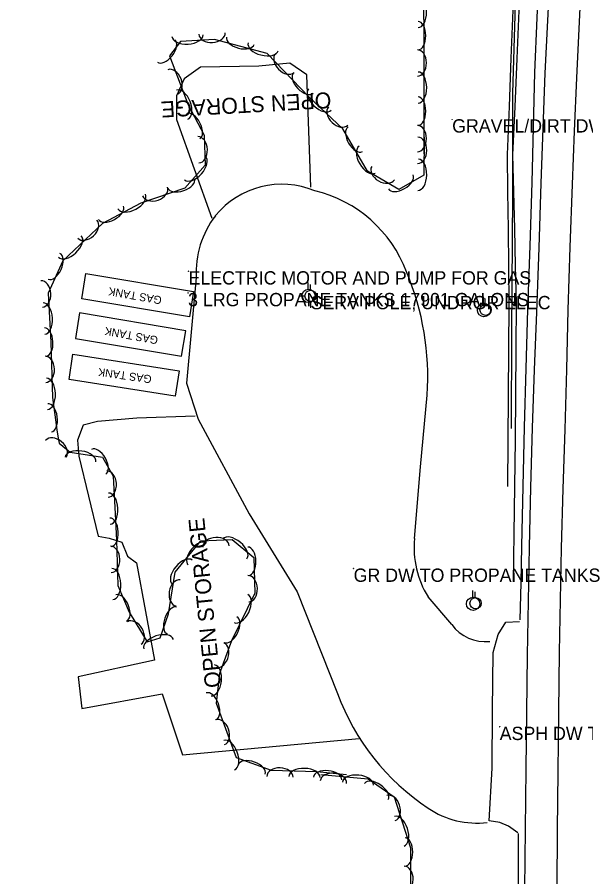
# Model space of a CAD drawing. Extents: x 954793 to 988390, y 1867850 to 1924428.
# Drawn here: x 960777.6 to 960991.5, y 1905142.2 to 1905465.6 of the extents above; entities that cross this region are included whole.
import ezdxf

# ---------------------------------------------------------------- set-up
doc = ezdxf.new("R2010")
doc.units = 0
for name, color, linetype in [('S_DITCHLINE', 7, 'Continuous'), ('S_DRIVEWAY', 7, 'Continuous'), ('S_EDGE_PAVEMENT', 7, 'Continuous'), ('S_MISC_BOUNDARY', 7, 'Continuous'), ('S_MISC_BOUNDARY_ANNOT', 7, 'Continuous'), ('S_MSC_PT_SYM', 7, 'Continuous'), ('S_PARKING', 7, 'Continuous'), ('S_PAVEMENT_CROWN', 7, 'Continuous'), ('S_SHOULDER', 7, 'Continuous'), ('S_STREAM', 7, 'Continuous'), ('S_SURVEY_TEXT_ANNOT', 7, 'Continuous'), ('S_TANK', 7, 'Continuous'), ('S_TANK_ANNOT', 7, 'Continuous'), ('S_TREE', 7, 'Continuous'), ('S_UTILITY_POLE', 7, 'Continuous'), ('S_UTILITY_POLE_ANNOT', 7, 'Continuous')]:
    doc.layers.add(name, color=color, linetype=linetype)

msp = doc.modelspace()

# ---------------------------------------------------------------- linework, layer by layer
at = {"layer": 'S_DITCHLINE'}
for points in [[(960962.25, 1905289.04), (960962.35, 1905306.2), (960962.45, 1905323.37), (960962.55, 1905340.53), (960962.65, 1905357.7), (960962.51, 1905371.75), (960962.38, 1905385.8), (960962.24, 1905399.85), (960962.1, 1905413.9), (960962.8, 1905432.03), (960963.49, 1905450.16), (960964.19, 1905468.29), (960964.88, 1905486.43), (960966.76, 1905510.29), (960968.63, 1905534.15)], [(960964.36, 1905253.1), (960964.62, 1905271.14), (960964.88, 1905289.19), (960965.02, 1905306.4), (960965.15, 1905323.62), (960965.29, 1905340.84), (960965.42, 1905358.06), (960965.09, 1905371.99), (960964.76, 1905385.92), (960964.43, 1905399.86), (960964.1, 1905413.79), (960964.91, 1905431.9), (960965.71, 1905450.02), (960966.51, 1905468.14), (960967.32, 1905486.25), (960968.34, 1905510.11), (960969.37, 1905533.98)]]:
    msp.add_lwpolyline(points, dxfattribs=at)
at = {"layer": 'S_DRIVEWAY'}
msp.add_lwpolyline([(960965.96, 1905158.68), (960962.44, 1905161.19), (960959.2, 1905162.58), (960955.21, 1905163.24), (960956.28, 1905183.02), (960956.45, 1905204.76), (960956.63, 1905226.51), (960958.57, 1905233.38), (960961.39, 1905237.96), (960966.56, 1905238.26)], dxfattribs=at)
at = {"layer": 'S_EDGE_PAVEMENT'}
msp.add_lwpolyline([(960968.57, 1905137.51), (960968.84, 1905160.09), (960969.11, 1905182.67), (960969.36, 1905204.08), (960969.61, 1905225.49), (960969.95, 1905245.86), (960970.29, 1905266.23), (960970.88, 1905288.65), (960971.46, 1905311.08), (960972.28, 1905332.87), (960973.1, 1905354.65), (960973.92, 1905378.86), (960974.74, 1905403.08), (960975.48, 1905423.82), (960976.22, 1905444.57), (960977.2, 1905464.29), (960978.18, 1905484.02)], dxfattribs=at)
at = {"layer": 'S_MISC_BOUNDARY'}
for points in [[(960888.11, 1905401.65), (960886.59, 1905443.88), (960880.21, 1905448.32), (960868.47, 1905447.14), (960846.57, 1905446.77), (960840.41, 1905442.41), (960837.55, 1905435.94), (960837.51, 1905427.15), (960850.82, 1905389.99)], [(960844.6, 1905315.42), (960822.58, 1905314.75), (960807.79, 1905313.46), (960802.37, 1905312.1), (960800.25, 1905306.44), (960800.76, 1905300.43), (960807.99, 1905270.34), (960812.19, 1905269.6), (960816.96, 1905268.03), (960819.1, 1905262.78), (960822.5, 1905260.23), (960829.21, 1905223.61), (960800.53, 1905217.36), (960801.96, 1905205.5), (960832.13, 1905211), (960839.76, 1905188.11), (960906.22, 1905194.2)]]:
    msp.add_lwpolyline(points, dxfattribs=at)
at = {"layer": 'S_MSC_PT_SYM'}
for points in [[(960941.25, 1905427.19), (960941.25, 1905427.24), (960941.25, 1905427.19), (960941.2, 1905427.19), (960941.25, 1905427.19), (960941.25, 1905427.14), (960941.25, 1905427.19), (960941.3, 1905427.19)], [(960941.25, 1905427.19), (960941.25, 1905427.24), (960941.25, 1905427.19), (960941.2, 1905427.19), (960941.25, 1905427.19), (960941.25, 1905427.14), (960941.25, 1905427.19), (960941.3, 1905427.19)], [(960842.05, 1905370.01), (960842.05, 1905370.06), (960842.05, 1905370.01), (960842, 1905370.01), (960842.05, 1905370.01), (960842.05, 1905369.96), (960842.05, 1905370.01), (960842.1, 1905370.01)], [(960842.05, 1905370.01), (960842.05, 1905370.06), (960842.05, 1905370.01), (960842, 1905370.01), (960842.05, 1905370.01), (960842.05, 1905369.96), (960842.05, 1905370.01), (960842.1, 1905370.01)], [(960841.88, 1905361.83), (960841.88, 1905361.88), (960841.88, 1905361.83), (960841.83, 1905361.83), (960841.88, 1905361.83), (960841.88, 1905361.78), (960841.88, 1905361.83), (960841.93, 1905361.83)], [(960841.88, 1905361.83), (960841.88, 1905361.88), (960841.88, 1905361.83), (960841.83, 1905361.83), (960841.88, 1905361.83), (960841.88, 1905361.78), (960841.88, 1905361.83), (960841.93, 1905361.83)], [(960904.16, 1905258.14), (960904.16, 1905258.19), (960904.16, 1905258.14), (960904.11, 1905258.14), (960904.16, 1905258.14), (960904.16, 1905258.09), (960904.16, 1905258.14), (960904.21, 1905258.14)], [(960904.16, 1905258.14), (960904.16, 1905258.19), (960904.16, 1905258.14), (960904.11, 1905258.14), (960904.16, 1905258.14), (960904.16, 1905258.09), (960904.16, 1905258.14), (960904.21, 1905258.14)], [(960959.13, 1905198.61), (960959.13, 1905198.66), (960959.13, 1905198.61), (960959.08, 1905198.61), (960959.13, 1905198.61), (960959.13, 1905198.56), (960959.13, 1905198.61), (960959.18, 1905198.61)], [(960959.13, 1905198.61), (960959.13, 1905198.66), (960959.13, 1905198.61), (960959.08, 1905198.61), (960959.13, 1905198.61), (960959.13, 1905198.56), (960959.13, 1905198.61), (960959.18, 1905198.61)]]:
    msp.add_lwpolyline(points, close=True, dxfattribs=at)
for points in [[(960941.25, 1905427.19), (960941.25, 1905427.24), (960941.25, 1905427.19), (960941.2, 1905427.19), (960941.25, 1905427.19), (960941.25, 1905427.14), (960941.25, 1905427.19), (960941.3, 1905427.19)], [(960842.05, 1905370.01), (960842.05, 1905370.06), (960842.05, 1905370.01), (960842, 1905370.01), (960842.05, 1905370.01), (960842.05, 1905369.96), (960842.05, 1905370.01), (960842.1, 1905370.01)], [(960841.88, 1905361.83), (960841.88, 1905361.88), (960841.88, 1905361.83), (960841.83, 1905361.83), (960841.88, 1905361.83), (960841.88, 1905361.78), (960841.88, 1905361.83), (960841.93, 1905361.83)], [(960904.16, 1905258.14), (960904.16, 1905258.19), (960904.16, 1905258.14), (960904.11, 1905258.14), (960904.16, 1905258.14), (960904.16, 1905258.09), (960904.16, 1905258.14), (960904.21, 1905258.14)], [(960959.13, 1905198.61), (960959.13, 1905198.66), (960959.13, 1905198.61), (960959.08, 1905198.61), (960959.13, 1905198.61), (960959.13, 1905198.56), (960959.13, 1905198.61), (960959.18, 1905198.61)]]:
    msp.add_lwpolyline(points, dxfattribs=at)
at = {"layer": 'S_PARKING'}
for points in [[(960844.9, 1905367.61), (960841.33, 1905327.92), (960845.73, 1905314.36), (960864.84, 1905278.69), (960882.95, 1905249.41), (960898.11, 1905211.09)], [(960927.08, 1905269.42), (960929.37, 1905296.47), (960931.83, 1905323.4)], [(960941.07, 1905237.09), (960932.16, 1905247.49)]]:
    msp.add_lwpolyline(points, dxfattribs=at)
for centre, major_axis, ratio, start_param, end_param in [((960877.15, 1905370.45), (-30.22, 11.41), 0.999417, 4.678511, 5.959478), ((960878.14, 1905352.59), (47.51, -12.19), 0.999167, 0.608462, 1.586527), ((960880.52, 1905369.32), (-19.46, -29.91), 0.998771, 4.639687, 5.336483), ((960830.07, 1905330.27), (101.76, -6.74), 0.998572, 6.281863, 6.747162), ((960962.16, 1905266), (-14.99, -31.92), 0.99933, 5.054117, 5.704113), ((960953.83, 1905246.41), (15.34, -3.87), 0.997077, 4.02088, 5.058528), ((960981.47, 1905242.01), (-84.74, -26.93), 0.999701, 0.047595, 0.676082), ((960950.24, 1905194.25), (16.92, -27.02), 0.998921, 5.121542, 5.856114)]:
    msp.add_ellipse(centre, major_axis=major_axis, ratio=ratio, start_param=start_param, end_param=end_param, dxfattribs=at)
at = {"layer": 'S_PAVEMENT_CROWN'}
msp.add_lwpolyline([(960980.73, 1905137.93), (960980.92, 1905159.8), (960981.12, 1905181.66), (960981.37, 1905204.18), (960981.63, 1905226.69), (960981.99, 1905246.28), (960982.35, 1905265.87), (960983.05, 1905288.18), (960983.75, 1905310.5), (960984.33, 1905333), (960984.91, 1905355.51), (960985.69, 1905379.07), (960986.48, 1905402.63), (960987.32, 1905422.69), (960988.17, 1905442.76), (960989.18, 1905463.82), (960990.18, 1905484.88)], dxfattribs=at)
at = {"layer": 'S_SHOULDER'}
for points in [[(960966.85, 1905238.82), (960967.17, 1905252.72), (960967.48, 1905266.62), (960967.99, 1905288.96), (960968.5, 1905311.3), (960969.14, 1905333.47), (960969.77, 1905355.63), (960970.56, 1905379.53), (960971.34, 1905403.42), (960971.83, 1905424.1), (960972.32, 1905444.78), (960973.2, 1905465.4), (960974.09, 1905486.02), (960976.1, 1905506.29), (960978.12, 1905526.56)], [(960963.17, 1904915.31), (960963.22, 1904937.83), (960963.26, 1904960.35), (960963.55, 1904982.61), (960963.84, 1905004.88), (960964.11, 1905021.51), (960959.69, 1905028.49), (960959.25, 1905050.67), (960959.81, 1905066.98), (960963, 1905077.81), (960965.35, 1905079.87), (960965.42, 1905094.44), (960965.8, 1905116.05), (960966.18, 1905137.66), (960966.2, 1905158.48)]]:
    msp.add_lwpolyline(points, dxfattribs=at)
at = {"layer": 'S_STREAM'}
msp.add_lwpolyline([(960968.5, 1905534.51), (960967.21, 1905508.92), (960964.97, 1905470.47), (960963.93, 1905436.95), (960963.93, 1905398.69), (960963.58, 1905346.97), (960963.44, 1905310.79)], dxfattribs=at)
at = {"layer": 'S_TANK'}
for points in [[(960803.46, 1905369.18), (960843.97, 1905362.35), (960842.35, 1905352.79), (960801.85, 1905359.63)], [(960841.02, 1905347.62), (960801.07, 1905354.32), (960799.46, 1905344.74), (960839.42, 1905338.05)], [(960798.56, 1905338.74), (960838.53, 1905332.55), (960837.05, 1905323.03), (960797.08, 1905329.22)]]:
    msp.add_lwpolyline(points, close=True, dxfattribs=at)
at = {"layer": 'S_TREE'}
for points in [[(960777.58, 1905549.31), (960924.97, 1905530.2), (960929.07, 1905526.55), (960930.46, 1905515.29), (960930.57, 1905414.19)], [(960930.77, 1905420.43), (960930.55, 1905406.1), (960921.13, 1905400.74), (960909.38, 1905407.6), (960900.07, 1905423.52), (960887.48, 1905435.44), (960871.59, 1905451.9), (960851.77, 1905457.13), (960839.04, 1905456.4), (960834.85, 1905451), (960841.92, 1905432.62), (960847.92, 1905421.19), (960848.36, 1905409.97), (960840.64, 1905401.27), (960824.09, 1905395.64), (960809.7, 1905387.94), (960794.7, 1905373.86), (960789.19, 1905361.74), (960790.27, 1905343.36), (960790.91, 1905322.46), (960792.52, 1905310.28), (960793.05, 1905307.22), (960793.32, 1905305.34), (960797.54, 1905301.9), (960809.66, 1905300.07), (960813.74, 1905292.9), (960814.49, 1905278.7), (960815, 1905268.82), (960815.48, 1905251.81), (960819.67, 1905241.71), (960826.43, 1905230.54), (960831.4, 1905232.13), (960834.47, 1905241.08), (960836.98, 1905256.77), (960846.72, 1905268.59), (960858.49, 1905269.11), (960866.59, 1905262.3), (960867, 1905248.86), (960858.19, 1905230.93), (960853.64, 1905218.7), (960852.39, 1905207.51), (960859.97, 1905186.99), (960873.16, 1905182.24), (960890.35, 1905181.72), (960901.46, 1905180.64)], [(960891.82, 1905180.6), (960909.64, 1905178.99), (960919.38, 1905172.28), (960925.62, 1905153.02), (960925.52, 1905135.26), (960922.35, 1905123.29), (960908.26, 1905090.7)]]:
    msp.add_lwpolyline(points, dxfattribs=at)
for centre, major_axis, ratio in [((960928.39, 1905467.52), (-0.01, 5.87), 0.55008), ((960928.4, 1905458.65), (-0.01, 5.35), 0.540699), ((960841.66, 1905458.67), (5.86, 0.34), 0.55008), ((960850.89, 1905459.47), (4.95, 0.29), 0.685311), ((960833.61, 1905452.87), (3.28, 4.23), 0.540699), ((960861.56, 1905456.74), (5.17, -1.37), 0.540699), ((960870.13, 1905454.48), (5.67, -1.5), 0.55008), ((960928.15, 1905448.35), (-0.01, 4.96), 0.685311), ((960878.3, 1905448.38), (3.44, -3.56), 0.685311), ((960836.07, 1905441.2), (-1.78, 4.62), 0.685311), ((960885.27, 1905440.79), (3.71, -3.85), 0.540699), ((960928.42, 1905439.09), (-0.01, 5.87), 0.55008), ((960839.64, 1905432.65), (-2.11, 5.48), 0.55008), ((960891.47, 1905434.59), (4.26, -4.03), 0.55008), ((960928.43, 1905430.22), (-0.01, 5.35), 0.540699), ((960843.77, 1905424.53), (-2.49, 4.73), 0.540699), ((960898.37, 1905428.41), (3.6, -3.41), 0.685311), ((960904.78, 1905419.66), (2.7, -4.62), 0.540699), ((960928.18, 1905419.92), (-0.01, 4.96), 0.685311), ((960845.75, 1905415.69), (-0.19, 4.95), 0.685311), ((960928.31, 1905415.51), (0.07, 4.95), 0.685311), ((960909.26, 1905412.01), (2.96, -5.07), 0.55008), ((960844.48, 1905408.8), (3.9, 4.39), 0.55008), ((960928.43, 1905406.25), (0.09, 5.87), 0.55008), ((960915.24, 1905406.94), (4.28, -2.5), 0.685311), ((960839.31, 1905403.06), (5.06, 1.72), 0.540699), ((960921.9, 1905403.62), (4.65, 2.64), 0.540699), ((960829.47, 1905399.99), (4.69, 1.6), 0.685311), ((960820.65, 1905396.21), (5.17, 2.77), 0.55008), ((960812.83, 1905392.02), (4.71, 2.52), 0.540699), ((960803.98, 1905385.83), (3.61, 3.39), 0.685311), ((960797.41, 1905379.3), (4.28, 4.02), 0.55008), ((960791.46, 1905371.85), (2.21, 4.87), 0.540699), ((960786.82, 1905361.44), (-0.29, 4.95), 0.685311), ((960787.63, 1905352.21), (-0.34, 5.86), 0.55008), ((960788.15, 1905343.36), (-0.31, 5.34), 0.540699), ((960788.2, 1905333.11), (-0.15, 4.95), 0.685311), ((960788.74, 1905323.86), (-0.18, 5.87), 0.55008), ((960789.78, 1905314.85), (-0.7, 5.3), 0.540699), ((960792.13, 1905303.23), (-3.84, 3.13), 0.685311), ((960808.23, 1905298.3), (-2.65, 4.65), 0.540699), ((960801.4, 1905299.17), (-5.8, 0.87), 0.55008), ((960811.52, 1905289.9), (-0.26, 4.95), 0.685311), ((960812.26, 1905280.67), (-0.31, 5.86), 0.55008), ((960812.72, 1905271.81), (-0.28, 5.34), 0.540699), ((960845.36, 1905263.6), (-3.4, -4.12), 0.540699), ((960852.41, 1905266.45), (-4.95, -0.22), 0.685311), ((960859.48, 1905265.51), (-4.49, 3.77), 0.55008), ((960812.82, 1905261.56), (-0.14, 4.95), 0.685311), ((960864.52, 1905260.88), (-0.16, 5.34), 0.540699), ((960839.72, 1905256.76), (-3.73, -4.53), 0.55008), ((960813.35, 1905252.31), (-0.17, 5.87), 0.55008), ((960864.57, 1905250.57), (-0.15, 4.95), 0.685311), ((960838.14, 1905248.97), (-0.78, -4.89), 0.685311), ((960816.71, 1905243.32), (-2.05, 4.94), 0.540699), ((960861.8, 1905243.09), (2.59, 5.27), 0.55008), ((960835.85, 1905238.56), (-1.73, -5.06), 0.540699), ((960821.61, 1905233.91), (-2.56, 4.24), 0.685311), ((960857.89, 1905235.13), (2.36, 4.8), 0.540699), ((960830.77, 1905229.7), (-5.59, -1.79), 0.55008), ((960853.63, 1905225.52), (1.73, 4.64), 0.685311), ((960851.21, 1905216.08), (0.65, 5.83), 0.55008), ((960850.57, 1905206.32), (-1.85, 5.02), 0.540699), ((960853.89, 1905196.57), (-1.72, 4.65), 0.685311), ((960857.34, 1905187.97), (-2.03, 5.51), 0.55008), ((960865.87, 1905182.61), (-5.03, 1.81), 0.540699), ((960876.41, 1905179.76), (-4.95, 0.15), 0.685311), ((960885.67, 1905179.74), (-5.87, 0.18), 0.55008), ((960894.38, 1905179.19), (-5.32, 0.52), 0.540699), ((960896.55, 1905177.78), (-4.94, 0.45), 0.685311), ((960905.79, 1905177.21), (-5.84, 0.53), 0.55008), ((960912.72, 1905174.3), (-4.4, 3.03), 0.540699), ((960918.25, 1905168.06), (-1.53, 4.71), 0.685311), ((960921.35, 1905159.33), (-1.81, 5.58), 0.55008), ((960923.49, 1905151.48), (0.03, 5.35), 0.540699), ((960923.17, 1905141.18), (0.03, 4.96), 0.685311)]:
    msp.add_ellipse(centre, major_axis=major_axis, ratio=ratio, start_param=3.141593, end_param=6.283185, dxfattribs=at)
at = {"layer": 'S_UTILITY_POLE'}
for p, q in [((960887.03, 1905363.23), (960887.03, 1905365.71)), ((960887.99, 1905362.81), (960887.99, 1905365.06)), ((960885.9, 1905360.68), (960883.57, 1905360.68)), ((960953.07, 1905357.91), (960953.07, 1905360.39)), ((960953.7, 1905357.67), (960953.7, 1905359.78)), ((960888.07, 1905356.26), (960888.07, 1905358.58)), ((960948.96, 1905247.4), (960948.96, 1905249.88)), ((960949.94, 1905247.23), (960949.94, 1905249.34))]:
    msp.add_line(p, q, dxfattribs=at)
for centre, radius in [((960887.18, 1905360.71), 2.5), ((960887.99, 1905360.7), 2.13), ((960953.22, 1905355.39), 2.5), ((960953.82, 1905355.53), 2.13), ((960949.1, 1905244.88), 2.5), ((960950.06, 1905245.09), 2.13)]:
    msp.add_circle(centre, radius, dxfattribs=at)

# ---------------------------------------------------------------- texts
at = {"layer": 'S_MISC_BOUNDARY_ANNOT'}
for rotation, p in [(183.2388, (960895.58, 1905437.42)), (95.6807, (960854.3, 1905213.55))]:
    msp.add_text('OPEN STORAGE', height=6.0005, rotation=rotation, dxfattribs=at).set_placement(p)
at = {"layer": 'S_SURVEY_TEXT_ANNOT'}
for s, p in [('GRAVEL/DIRT DW', (960941.25, 1905422.19)), ('ELECTRIC MOTOR AND PUMP FOR GAS', (960842.05, 1905365.01)), ('3 LRG PROPANE TANKS 17901 GALONS', (960841.88, 1905356.83)), ('GR DW TO PROPANE TANKS', (960904.16, 1905253.14)), ('ASPH DW TO PK NO CUS', (960959.13, 1905193.61))]:
    msp.add_text(s, height=5, dxfattribs=at).set_placement(p)
at = {"layer": 'S_TANK_ANNOT'}
for rotation, p in [(169.9345, (960832.18, 1905360.44)), (169.6925, (960830.76, 1905345.42)), (171.9096, (960828.34, 1905330.77))]:
    msp.add_text('GAS TANK', height=3, rotation=rotation, dxfattribs=at).set_placement(p)
at = {"layer": 'S_UTILITY_POLE_ANNOT'}
msp.add_text('SERV POLE, UNDRGR ELEC', height=5, dxfattribs=at).set_placement((960887.99, 1905355.7))

doc.saveas('drawing.dxf')
